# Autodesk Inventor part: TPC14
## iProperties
Shininess: 64.0
Length Units: 11272
Angle Units: 11279
Time Units: 11290
Mass Units: 11286
Length Display Precision: 3
Angle Display Precision: 2
Compacted: True
Part Number: TPC14
Document SubType Name: Modeling
Created: 2004-08
Designer: Lori
Manufacturer: Standard
Standards Organization: Custom
Density: 0.0
Volumn: 0.0
Area: 0.0
PropertySet Name: Model Information
Control State: 0
Master: False
Checked Out: False
Author: Lori
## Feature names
1. Base1
